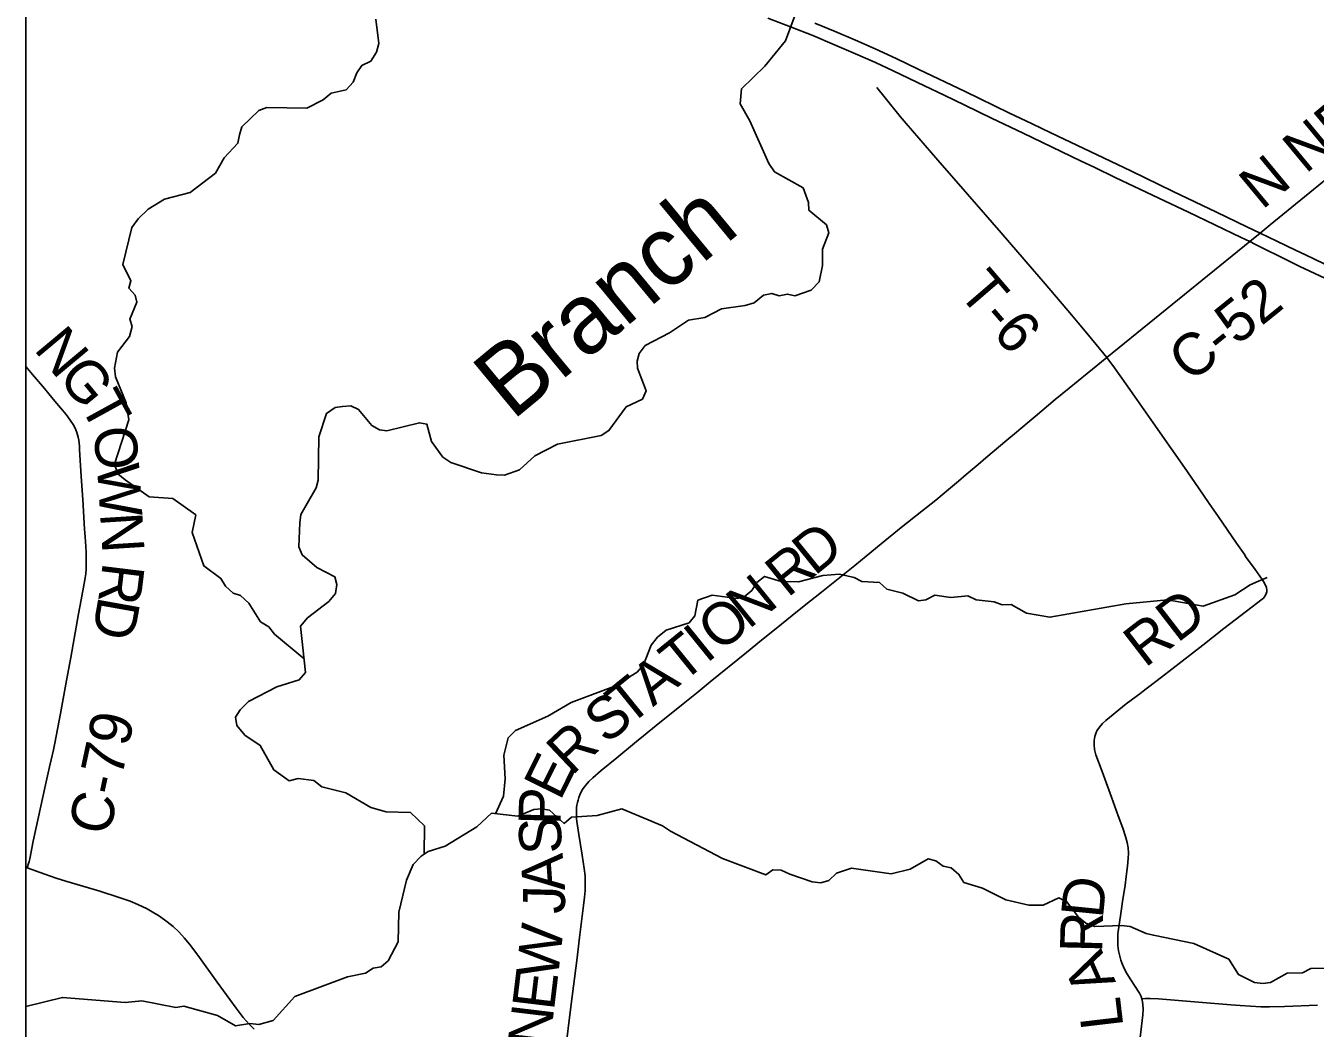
# Model space of a CAD drawing. Extents: x -49 to -8.2, y 9.4 to 23.5.
# Drawn here: x -14.966 to -14.098, y 12.687 to 13.362 of the extents above; entities that cross this region are included whole.
import ezdxf

# ---------------------------------------------------------------- set-up
doc = ezdxf.new("R2010")
doc.units = 0
for name, color, linetype in [('GM_X_Adjacent_County', 7, 'Continuous'), ('GM_X_County_Road', 7, 'Continuous'), ('GM_X_County_Road_Text', 7, 'Continuous'), ('GM_X_Minor_River', 7, 'Continuous'), ('GM_X_Minor_River_Text', 7, 'Continuous'), ('GM_X_Township_Road', 7, 'Continuous'), ('GM_X_Township_Road_Text', 7, 'Continuous'), ('GM_X_US_Route', 7, 'Continuous')]:
    doc.layers.add(name, color=color, linetype=linetype)

msp = doc.modelspace()

# ---------------------------------------------------------------- linework, layer by layer
at = {"layer": 'GM_X_Adjacent_County'}
msp.add_lwpolyline([(-14.96621, 16.20866), (-8.16621, 16.20866), (-8.16621, 9.40866), (-14.96621, 9.40866)], close=True, dxfattribs=at)
at = {"layer": 'GM_X_County_Road'}
for points in [[(-14.23818, 13.13856), (-14.14204, 13.21669), (-14.13502, 13.22239), (-14.12817, 13.22796), (-14.10509, 13.24685), (-14.07987, 13.26752)], [(-14.34487, 13.04968), (-14.34483, 13.04972), (-14.33817, 13.05543), (-14.333, 13.05982), (-14.32499, 13.06666), (-14.31981, 13.07112), (-14.30561, 13.08304), (-14.29916, 13.08841), (-14.292, 13.09438), (-14.28653, 13.09896), (-14.27293, 13.11031), (-14.26358, 13.11801), (-14.2516, 13.1279), (-14.23818, 13.13856)], [(-14.94918, 12.86754), (-14.94765, 12.87439), (-14.94671, 12.87895), (-14.9429, 12.89879), (-14.93873, 12.92107), (-14.93583, 12.93665), (-14.93061, 12.96598), (-14.92885, 12.97544), (-14.92682, 12.98645), (-14.92624, 12.99014), (-14.92587, 12.99293), (-14.92557, 12.99636), (-14.92544, 13.00166), (-14.92559, 13.00758), (-14.92604, 13.01472), (-14.92623, 13.01779), (-14.92656, 13.02305), (-14.92777, 13.04295), (-14.92883, 13.05839), (-14.93002, 13.07678), (-14.93013, 13.07889), (-14.93058, 13.08287), (-14.93089, 13.085), (-14.93132, 13.08658), (-14.93177, 13.08811), (-14.93245, 13.08984), (-14.93302, 13.091), (-14.93439, 13.09347), (-14.93624, 13.09637), (-14.93902, 13.10015), (-14.94655, 13.10926), (-14.95071, 13.11426), (-14.95371, 13.11782), (-14.96176, 13.12729), (-14.96621, 13.13254)], [(-14.60318, 12.66838), (-14.59889, 12.70292), (-14.59514, 12.73251), (-14.59325, 12.74793), (-14.59213, 12.75686), (-14.5907, 12.7695), (-14.59001, 12.7752), (-14.58964, 12.77967), (-14.58946, 12.7843), (-14.58962, 12.78954), (-14.59011, 12.79445), (-14.59149, 12.80333), (-14.59386, 12.81742), (-14.5951, 12.82605), (-14.5953, 12.8281), (-14.59542, 12.83), (-14.59547, 12.83195), (-14.59542, 12.83358), (-14.5953, 12.83553), (-14.59514, 12.8371), (-14.5948, 12.83883), (-14.59435, 12.8405), (-14.5938, 12.84218), (-14.59313, 12.84402), (-14.59212, 12.84598), (-14.59122, 12.8476), (-14.59016, 12.84916), (-14.58911, 12.85048), (-14.58712, 12.85292), (-14.58446, 12.8556), (-14.57873, 12.86041), (-14.56817, 12.86907), (-14.55621, 12.87895), (-14.54176, 12.89072), (-14.5236, 12.90531), (-14.51343, 12.91347), (-14.50525, 12.92015), (-14.48096, 12.94002), (-14.4708, 12.94821), (-14.46089, 12.95619), (-14.45024, 12.96477), (-14.44197, 12.97134), (-14.43033, 12.98066), (-14.41579, 12.9923), (-14.40803, 12.99851), (-14.40028, 13.00473), (-14.39022, 13.01303), (-14.37679, 13.02407), (-14.36291, 13.03509), (-14.35344, 13.04262), (-14.34487, 13.04968)], [(-14.96525, 12.79482), (-14.96435, 12.7978), (-14.96396, 12.79915), (-14.96356, 12.80096), (-14.96117, 12.81282), (-14.95303, 12.85078), (-14.95022, 12.86288), (-14.94918, 12.86754)], [(-14.96621, 12.79517), (-14.96571, 12.79498), (-14.96525, 12.79482)], [(-14.96525, 12.79482), (-14.95344, 12.79058), (-14.94579, 12.78801), (-14.93928, 12.78597), (-14.91636, 12.77911), (-14.9033, 12.77498), (-14.89594, 12.77236), (-14.89075, 12.7702), (-14.88456, 12.76724), (-14.881, 12.76531), (-14.87624, 12.76232), (-14.87091, 12.75851), (-14.86705, 12.75533), (-14.8632, 12.75167), (-14.85938, 12.74755), (-14.85503, 12.74225), (-14.84927, 12.73451), (-14.83738, 12.7178), (-14.82455, 12.70025), (-14.81979, 12.69414), (-14.81772, 12.69174), (-14.81573, 12.68948), (-14.81247, 12.6862)]]:
    msp.add_lwpolyline(points, dxfattribs=at)
at = {"layer": 'GM_X_Minor_River'}
for points in [[(-14.69797, 12.80412), (-14.69782, 12.82323), (-14.70716, 12.83211), (-14.72346, 12.83254), (-14.73385, 12.83555), (-14.75076, 12.8453), (-14.75699, 12.84691), (-14.76681, 12.84952), (-14.77225, 12.85359), (-14.78285, 12.85508), (-14.78894, 12.85347), (-14.79925, 12.86083), (-14.80829, 12.87729), (-14.8188, 12.88429), (-14.82401, 12.89082), (-14.82506, 12.89634), (-14.82176, 12.90141), (-14.81618, 12.90683), (-14.79726, 12.9168), (-14.78202, 12.9215), (-14.77777, 12.92656), (-14.78127, 12.95774), (-14.77645, 12.96317), (-14.76206, 12.97434), (-14.75762, 12.97959), (-14.75676, 12.98565), (-14.75801, 12.99098), (-14.77024, 12.99724), (-14.78016, 13.00575), (-14.78235, 13.01109), (-14.78172, 13.02722), (-14.78107, 13.0329), (-14.77074, 13.05078), (-14.76934, 13.05607), (-14.76889, 13.0853), (-14.76372, 13.10098), (-14.75797, 13.10507), (-14.75284, 13.10556), (-14.74733, 13.10604), (-14.74206, 13.10369), (-14.73313, 13.09273), (-14.72805, 13.08981), (-14.72313, 13.08935), (-14.70105, 13.09471), (-14.69614, 13.09369), (-14.6929, 13.08206), (-14.68548, 13.07151), (-14.68004, 13.06801), (-14.65929, 13.06105), (-14.64926, 13.05957), (-14.64376, 13.05948), (-14.63366, 13.06294), (-14.62346, 13.07246), (-14.60817, 13.0802), (-14.57869, 13.08621), (-14.57353, 13.08936), (-14.5619, 13.10532), (-14.55101, 13.11066), (-14.54847, 13.11612), (-14.5543, 13.1314), (-14.55461, 13.13615), (-14.5532, 13.14125), (-14.54913, 13.1467), (-14.5327, 13.15518), (-14.52005, 13.16372), (-14.50903, 13.16564), (-14.49775, 13.17154), (-14.48179, 13.17358), (-14.47569, 13.17538), (-14.46955, 13.1806), (-14.46384, 13.18185), (-14.45893, 13.18025), (-14.45323, 13.18131), (-14.44832, 13.18028), (-14.43745, 13.18391), (-14.43205, 13.18971), (-14.42961, 13.20069), (-14.42963, 13.2117), (-14.42548, 13.22265), (-14.42711, 13.22799), (-14.4389, 13.23785), (-14.4392, 13.24298), (-14.44284, 13.25291), (-14.46201, 13.26383), (-14.46591, 13.2694), (-14.47874, 13.29807), (-14.4852, 13.30956), (-14.48429, 13.31961), (-14.46851, 13.33494), (-14.45459, 13.35201), (-14.44529, 13.37731)], [(-14.7788, 12.93571), (-14.7988, 12.95231), (-14.80252, 12.95711), (-14.80815, 12.96062), (-14.81592, 12.97307), (-14.82172, 12.97828), (-14.82663, 12.97988), (-14.83168, 12.98451), (-14.83482, 12.98987), (-14.84626, 12.99821), (-14.85425, 13.02072), (-14.85161, 13.03264), (-14.86717, 13.0437), (-14.88308, 13.04489), (-14.89921, 13.05633), (-14.90427, 13.06039), (-14.90645, 13.06669), (-14.89689, 13.09673), (-14.89861, 13.10814), (-14.90574, 13.12553), (-14.9064, 13.13142), (-14.90434, 13.14221), (-14.89641, 13.15272), (-14.8946, 13.15953), (-14.89604, 13.16448), (-14.8915, 13.17581), (-14.89257, 13.18057), (-14.89685, 13.18538), (-14.89545, 13.19029), (-14.90097, 13.2012), (-14.8949, 13.22617), (-14.89045, 13.23198), (-14.8839, 13.23853), (-14.8728, 13.24539), (-14.85548, 13.24987), (-14.8384, 13.2629), (-14.83256, 13.27307), (-14.82331, 13.28299), (-14.82227, 13.28867), (-14.82067, 13.29396), (-14.80932, 13.30499), (-14.80379, 13.307), (-14.77706, 13.30659), (-14.76598, 13.31212), (-14.7606, 13.31678), (-14.75051, 13.31891), (-14.74569, 13.32415), (-14.74332, 13.33038), (-14.74002, 13.33527), (-14.73391, 13.33821), (-14.73003, 13.34423), (-14.72842, 13.35028), (-14.73044, 13.36664)], [(-14.64986, 12.83135), (-14.64461, 12.84311), (-14.64349, 12.85486), (-14.64438, 12.87082), (-14.64135, 12.88254), (-14.63635, 12.8874), (-14.61458, 12.89713), (-14.5989, 12.90619), (-14.57029, 12.91695), (-14.55459, 12.92677), (-14.55035, 12.93164), (-14.54502, 12.94485), (-14.54077, 12.95029), (-14.53501, 12.95495), (-14.51958, 12.95984), (-14.51571, 12.96471), (-14.51365, 12.97512), (-14.50412, 12.97858), (-14.48728, 12.97624), (-14.48252, 12.97749), (-14.47734, 12.98159), (-14.47384, 12.98704), (-14.46866, 12.99114), (-14.45752, 12.98774), (-14.44577, 12.98756), (-14.42959, 12.99168), (-14.4182, 12.99265), (-14.40837, 12.99041), (-14.40329, 12.98767), (-14.39136, 12.98711), (-14.38631, 12.98248), (-14.37573, 12.97985), (-14.365, 12.97475), (-14.36006, 12.97543), (-14.35414, 12.97857), (-14.34335, 12.97708), (-14.33196, 12.97804), (-14.32631, 12.9753), (-14.31401, 12.97416), (-14.30873, 12.97199), (-14.30266, 12.97228), (-14.29232, 12.96642), (-14.27662, 12.96372), (-14.22548, 12.97261), (-14.19738, 12.97541), (-14.17336, 12.97106), (-14.15201, 12.9787), (-14.14167, 12.98557), (-14.13613, 12.98795), (-14.13021, 12.99052)], [(-14.96621, 12.70148), (-14.94153, 12.70755), (-14.89931, 12.70407), (-14.8881, 12.70523), (-14.86522, 12.70089), (-14.85971, 12.70176), (-14.83706, 12.69534), (-14.82503, 12.68833), (-14.81534, 12.68989), (-14.80928, 12.68942), (-14.79957, 12.69193), (-14.7851, 12.70822), (-14.74963, 12.72134), (-14.73745, 12.72401), (-14.73228, 12.72734), (-14.72696, 12.72821), (-14.72216, 12.73231), (-14.71551, 12.74512), (-14.71502, 12.76504), (-14.70995, 12.7866), (-14.70542, 12.79716), (-14.70003, 12.80277), (-14.69524, 12.80592), (-14.68381, 12.80955), (-14.66256, 12.82251), (-14.65256, 12.83166), (-14.63496, 12.82968), (-14.62408, 12.83407), (-14.61915, 12.83456), (-14.61366, 12.83372), (-14.60375, 12.82484), (-14.59876, 12.82894), (-14.58148, 12.83019), (-14.56492, 12.8345), (-14.53741, 12.82307), (-14.53215, 12.81957), (-14.49698, 12.80119), (-14.46795, 12.79012), (-14.46315, 12.79347), (-14.45747, 12.79338), (-14.45163, 12.79063), (-14.43673, 12.78547), (-14.43086, 12.78481), (-14.42553, 12.78625), (-14.42034, 12.79129), (-14.41024, 12.79455), (-14.38337, 12.79092), (-14.37062, 12.79395), (-14.35856, 12.80098), (-14.35347, 12.79957), (-14.3484, 12.79589), (-14.34311, 12.79485), (-14.33787, 12.79041), (-14.33454, 12.78504), (-14.32208, 12.78106), (-14.30627, 12.77341), (-14.29078, 12.76976), (-14.28604, 12.76969), (-14.28111, 12.7698), (-14.27061, 12.77457), (-14.26533, 12.77222), (-14.25734, 12.76165), (-14.25229, 12.75759), (-14.24625, 12.75541), (-14.22842, 12.75609), (-14.22255, 12.75524), (-14.21181, 12.75071), (-14.2069, 12.74949), (-14.17968, 12.74395), (-14.15614, 12.73334), (-14.14948, 12.72299), (-14.13875, 12.7177), (-14.13326, 12.71704), (-14.12813, 12.71773), (-14.11685, 12.72401)], [(-14.11685, 12.72401), (-14.10642, 12.72423), (-14.10087, 12.72699), (-14.08987, 12.7272), (-14.06302, 12.73514), (-14.05072, 12.73362), (-14.04428, 12.73276), (-14.02876, 12.73101), (-14.00852, 12.74019), (-14.00363, 12.73783), (-13.98713, 12.73796), (-13.97677, 12.73363), (-13.97165, 12.73393), (-13.96333, 12.74443), (-13.94262, 12.75949), (-13.93262, 12.76882), (-13.91009, 12.77892), (-13.89526, 12.78192), (-13.88917, 12.78334), (-13.88399, 12.78744), (-13.87884, 12.78926), (-13.86898, 12.7893), (-13.85236, 12.79739), (-13.82586, 12.79433)]]:
    msp.add_lwpolyline(points, dxfattribs=at)
at = {"layer": 'GM_X_Township_Road'}
for points in [[(-14.23818, 13.13856), (-14.25066, 13.15365), (-14.25764, 13.16205), (-14.26207, 13.16745), (-14.27978, 13.18827), (-14.28835, 13.19811), (-14.30951, 13.22253), (-14.33201, 13.24866), (-14.35195, 13.27167), (-14.37338, 13.29625), (-14.37742, 13.30096), (-14.38753, 13.31351), (-14.39308, 13.3206)], [(-14.14543, 13.00563), (-14.15092, 13.01366), (-14.16309, 13.03131), (-14.16926, 13.04027), (-14.17648, 13.05075), (-14.18606, 13.06452), (-14.19495, 13.07726), (-14.20708, 13.09456), (-14.21814, 13.11033), (-14.22552, 13.12096), (-14.23315, 13.1316), (-14.23818, 13.13856)], [(-14.23533, 12.89704), (-14.2327, 12.89927), (-14.22523, 12.90531), (-14.2152, 12.91272), (-14.21474, 12.91313), (-14.20135, 12.92331), (-14.17371, 12.94496), (-14.15955, 12.9561), (-14.14424, 12.96781), (-14.13357, 12.97587), (-14.13286, 12.97656), (-14.13225, 12.97718), (-14.13152, 12.97818), (-14.13085, 12.97958), (-14.13054, 12.98076), (-14.13046, 12.98199), (-14.1308, 12.9838), (-14.13178, 12.98608), (-14.13281, 12.98775), (-14.1336, 12.989), (-14.13845, 12.99586), (-14.14478, 13.00469), (-14.14543, 13.00563)], [(-14.2167, 12.71109), (-14.21912, 12.71494), (-14.22209, 12.71931), (-14.22489, 12.72378), (-14.22659, 12.72709), (-14.22816, 12.7308), (-14.2288, 12.73271), (-14.22955, 12.73525), (-14.23034, 12.73889), (-14.23081, 12.74259), (-14.23094, 12.74631), (-14.23075, 12.75035), (-14.23002, 12.75652), (-14.22859, 12.76573), (-14.22763, 12.77219), (-14.22596, 12.78326), (-14.22513, 12.78911), (-14.22435, 12.79589), (-14.22378, 12.80113), (-14.22366, 12.80485), (-14.22392, 12.80824), (-14.22457, 12.81188), (-14.22565, 12.81608), (-14.22753, 12.82169), (-14.23061, 12.82988), (-14.23513, 12.84245), (-14.2414, 12.85969), (-14.24555, 12.87108), (-14.24652, 12.87467), (-14.24689, 12.87776), (-14.24683, 12.88055), (-14.24635, 12.88331), (-14.24567, 12.88537), (-14.24489, 12.88705), (-14.24323, 12.88964), (-14.24116, 12.89199), (-14.23884, 12.89405), (-14.23635, 12.89617), (-14.23533, 12.89704)], [(-14.24641, 12.4123), (-14.24591, 12.41354), (-14.24541, 12.41476), (-14.24506, 12.41588), (-14.2449, 12.41687), (-14.24162, 12.44774), (-14.23872, 12.475), (-14.23417, 12.51638), (-14.23032, 12.55159), (-14.22408, 12.60966), (-14.21798, 12.6615), (-14.21398, 12.69577), (-14.21374, 12.69948), (-14.21391, 12.7027), (-14.21452, 12.70591), (-14.2147, 12.70654)], [(-14.2147, 12.70654), (-14.21517, 12.7082), (-14.21632, 12.71049), (-14.2167, 12.71109)], [(-14.2147, 12.70654), (-14.21245, 12.70679), (-14.20899, 12.70679), (-14.20341, 12.70663), (-14.17658, 12.70444), (-14.15475, 12.70265), (-14.14857, 12.70214), (-14.13463, 12.7013), (-14.12875, 12.70116), (-14.11852, 12.70134), (-14.09649, 12.70237)]]:
    msp.add_lwpolyline(points, dxfattribs=at)
at = {"layer": 'GM_X_US_Route'}
for points in [[(-14.46645, 13.36719), (-14.45133, 13.36148), (-14.43633, 13.35546), (-14.42171, 13.34935), (-14.40743, 13.34321), (-14.39408, 13.33728), (-14.38223, 13.3318), (-14.36092, 13.32163), (-14.34776, 13.3153), (-14.33377, 13.30855), (-14.31585, 13.29993), (-14.29457, 13.28971), (-14.2559, 13.2712), (-14.24638, 13.26661), (-14.23266, 13.26001), (-14.20324, 13.24593), (-14.18333, 13.23644), (-14.14774, 13.2194), (-14.14204, 13.21669), (-14.13821, 13.21486), (-14.11541, 13.20355), (-14.10818, 13.19997), (-14.05788, 13.17628)], [(-14.43477, 13.36392), (-14.42129, 13.35834), (-14.40759, 13.35247), (-14.39426, 13.34653), (-14.38018, 13.33998), (-14.36479, 13.33256), (-14.33365, 13.31773), (-14.30428, 13.30353), (-14.28857, 13.29607), (-14.27595, 13.29005), (-14.25382, 13.27943), (-14.22214, 13.26431), (-14.1936, 13.25054), (-14.16444, 13.23661), (-14.14403, 13.22674), (-14.13502, 13.22239), (-14.12388, 13.21702), (-14.11129, 13.21094), (-14.10455, 13.20774), (-14.09895, 13.20506), (-14.09192, 13.20174)]]:
    msp.add_lwpolyline(points, dxfattribs=at)

# ---------------------------------------------------------------- texts
at = {"layer": 'GM_X_County_Road_Text'}
for s, height, rotation, p in [('N NEW JASPER', 0.0284091, 39.6314, (-14.1337, 13.23768)), ('C-52', 0.028409, 38.92719, (-14.18181, 13.12108)), ('N', 0.02841, 309.8802, (-14.96134, 13.14405)), ('G', 0.02841, 309.45857, (-14.94535, 13.12491)), ('T', 0.02841, 298.80028, (-14.93024, 13.10676)), ('O', 0.02841, 275.85667, (-14.9209, 13.09099)), ('W', 0.02841, 273.74047, (-14.91837, 13.0664)), ('N', 0.02841, 273.56862, (-14.91622, 13.03357)), ('D', 0.02841, 39.00002, (-14.43509, 12.99109)), ('R', 0.02841, 39.00298, (-14.45323, 12.97641)), ('R', 0.02841, 263.05119, (-14.91424, 13.00125)), ('N', 0.02841, 39.00057, (-14.47946, 12.95516)), ('D', 0.02841, 259.85675, (-14.917, 12.97851)), ('O', 0.02841, 39.00057, (-14.49888, 12.93943)), ('T', 0.02841, 39.00114, (-14.52446, 12.91871)), ('I', 0.02841, 38.99995, (-14.50795, 12.93209)), ('A', 0.02841, 39.00321, (-14.54389, 12.90298)), ('T', 0.02841, 39.00114, (-14.56041, 12.88961)), ('S', 0.02841, 39.01227, (-14.5753, 12.87754)), ('C-79', 0.028409, 77.95283, (-14.90999, 12.81577)), ('R', 0.02841, 43.41843, (-14.59859, 12.85636)), ('E', 0.02841, 63.78376, (-14.6064, 12.83943)), ('P', 0.02841, 88.54118, (-14.60612, 12.8234)), ('S', 0.02841, 94.22965, (-14.60473, 12.80503)), ('A', 0.02841, 93.86433, (-14.60303, 12.77988)), ('J', 0.02841, 88.55907, (-14.6033, 12.76368)), ('W', 0.02841, 83.31737, (-14.60803, 12.71944)), ('E', 0.02841, 83.13809, (-14.61058, 12.69824)), ('N', 0.02841, 83.13523, (-14.61357, 12.67342))]:
    msp.add_text(s, height=height, rotation=rotation, dxfattribs=at).set_placement(p)
at = {"layer": 'GM_X_Minor_River_Text'}
msp.add_text('Branch', height=0.047353, rotation=39.62482, dxfattribs=at).set_placement((-14.63864, 13.09558))
at = {"layer": 'GM_X_Township_Road_Text'}
for s, height, rotation, p in [('T-6', 0.028409, 310.65126, (-14.33925, 13.18225)), ('RD', 0.028409, 37.65757, (-14.21257, 12.92916)), ('D', 0.02841, 84.30064, (-14.24093, 12.76027)), ('R', 0.02841, 88.59872, (-14.24147, 12.73751)), ('A', 0.02841, 113.91364, (-14.23197, 12.71788)), ('L', 0.02841, 96.74599, (-14.22703, 12.68785))]:
    msp.add_text(s, height=height, rotation=rotation, dxfattribs=at).set_placement(p)

doc.saveas('drawing.dxf')
